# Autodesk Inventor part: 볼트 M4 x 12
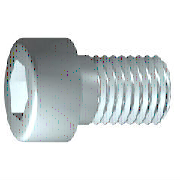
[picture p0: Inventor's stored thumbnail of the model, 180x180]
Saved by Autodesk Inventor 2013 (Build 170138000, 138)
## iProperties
IsCustomPart: 0
Created: 2012-02
Part Number: 볼트 M4 x 12
Material: 스테인리스강
Description: 6각 소켓 머리 캡 나사
Document SubType Name: Modeling
Standard: ISO 4762
Designer: mduedu
Standard Revision: Fourth edition 2004-03-01
Standards Organization: ISO
Language: ko-KR
Size Designation: M4 x 12
Categories: <MemberInstance><Categories><Category DisplayName="조임쇠" InternalName="e4da775c-781d-43d5-af7c-5136215cf5a6" Mnemonic="FSTN"><Category DisplayName="볼트" InternalN
Density: 8.08 g/cm^3
Mass: 2.29719 g
Surface Area: 3.30853 cm^2
Volume: 0.284306 cm^3
Author: mduedu
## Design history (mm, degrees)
sketch "스케치1"
  geometry: L1 (-1, 0)-(12, 0); L2 (12, 0)-(12, 2); L3 (12, 2)-(1.75, 2); L4 (1.75, 2)-(1.32, 2); L5 (1.32, 2)-(0, 2); L6 (0, 2)-(0, 3.5); L7 (0, 3.5)-(-4, 3.5); L8 (-4, 3.5)-(-4, 1.732); L9 (-4, 1.732)-(-2, 1.732); L10 (-2, 1.732)-(-1, 0); L11 (-7.2, 0)-(15.2, 0) reference; L12 (0, -0.7)-(0, 4.2) reference; L13 (1.75, 2)-(0, 2)
  constraints: 22 end point, 6 parallel, 2 collinear, 2 perpendicular, 1 horizontal, 1 point on line
  dimensions: "d1" = 10.25 distance from line of L3.end L2 (= GEL); "d2" = 0.42952 distance of L4.end L3.end (computed from GAL); "d3" = 4 distance between parallel lines of L8 L6 (= KOH); "d4" = 2 distance of L8.end L9.end (= INTI); "d5" = 60 deg angle of L10 L1; "d6" = 4 diameter of L3 L1 (= GD); "d7" = 4 diameter of L5 L1 (= BDM); "d8" = 3.4641 diameter of L9 L1 (= 1.1547 x SW); "d9" = 7 diameter of L7 L1 (= KOD); "d26" = 12 distance between parallel lines of L12 L2 (= NLG)
revolve "본체" sketch "스케치1" stored, may be unused: angle "d10" = 90 deg
sketch "스케치2"
  geometry: L1 (0, -4.9)-(0, 4.9) reference; L2 (-4.9, 0)-(4.9, 0) reference; L3 (1.732, 0)-(0.866, -1.5); L4 (0.866, -1.5)-(-0.866, -1.5); L5 (-0.866, -1.5)-(-1.732, 0); L6 (-1.732, 0)-(-0.866, 1.5); L7 (-0.866, 1.5)-(0.866, 1.5); L8 (0.866, 1.5)-(1.732, 0); 2 further points
  constraints: 12 end point, 1 coincident, 1 horizontal alignment, 1 point on line, 12 other
extrude "슬롯" join sketch "스케치2" stored distance "d11" = 10; taper "d12" = 0 deg
workplane "Work Plane1"
fillet "Fillet2" dims "d30" = 0.1 (= R)
body "Solid1"
fillet "모깎기1" dims "d17" = 0.4 (= RR)
feature "스레드" dims "d13" = 10.25 (= GEL), "d14" = 0
chamfer "모따기1" distance "d15" = 0.42941 (= -0.5 x SPD + 0.5 x GD); stored, may be unused: second distance "d16" = 0.42941 (= GUL), angle "d27" = 45 deg
other parameters: "GD" = 4 [user parameter; used in 2 equation terms], "NLG" = 12 [user parameter; used in 1 equation term], "GEL" = 10.25 [user parameter; used in 2 equation terms], "KOD" = 7 [user parameter; used in 1 equation term], "KOH" = 4 [user parameter; used in 1 equation term], "INTI" = 2 [user parameter; used in 1 equation term], "GAL" = 0.42941 (= 0.61345 x PTC) [user parameter; used in 1 equation term], "GUL" = 0.42941 (= 0.61345 x PTC) [user parameter; used in 1 equation term], "BDM" = 4 (= NND) [user parameter; used in 1 equation term], "SW" = 3 [user parameter; used in 2 equation terms], "RR" = 0.4 [user parameter; used in 1 equation term], "SPD" = 3.14117 (= NND - 1.2269 x PTC) [user parameter; used in 1 equation term], "d19" = 0, "d28" = 0, "d29" = 0, "R" = 0.1 [user parameter; used in 1 equation term], "TOA" = 30 deg [user parameter], "GD1" = 3.14117 (= THREADDIA - 1.2269 x PTC) [user parameter], "THREADDIA" = 4 [user parameter; used in 1 equation term], "FAWI" = 45 deg [user parameter], "TPU" = 14.28571 (computed from PTC) [user parameter], "PTC" = 0.7 [user parameter; used in 5 equation terms], "NND" = 4 [user parameter; used in 2 equation terms], "E0" = 3.465 (= 1.155 x SW) [user parameter]
